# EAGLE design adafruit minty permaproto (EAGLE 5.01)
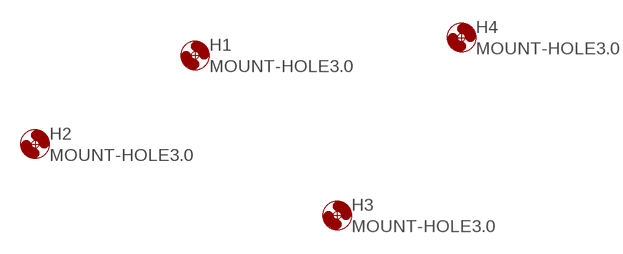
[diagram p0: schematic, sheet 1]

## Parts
H1  MOUNT-HOLE3.0  [3,0]
H2  MOUNT-HOLE3.0  [3,0]
H3  MOUNT-HOLE3.0  [3,0]
H4  MOUNT-HOLE3.0  [3,0]

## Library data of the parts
H1-H4 = holes:MOUNT-HOLE: MOUNTING HOLE with drill center marker

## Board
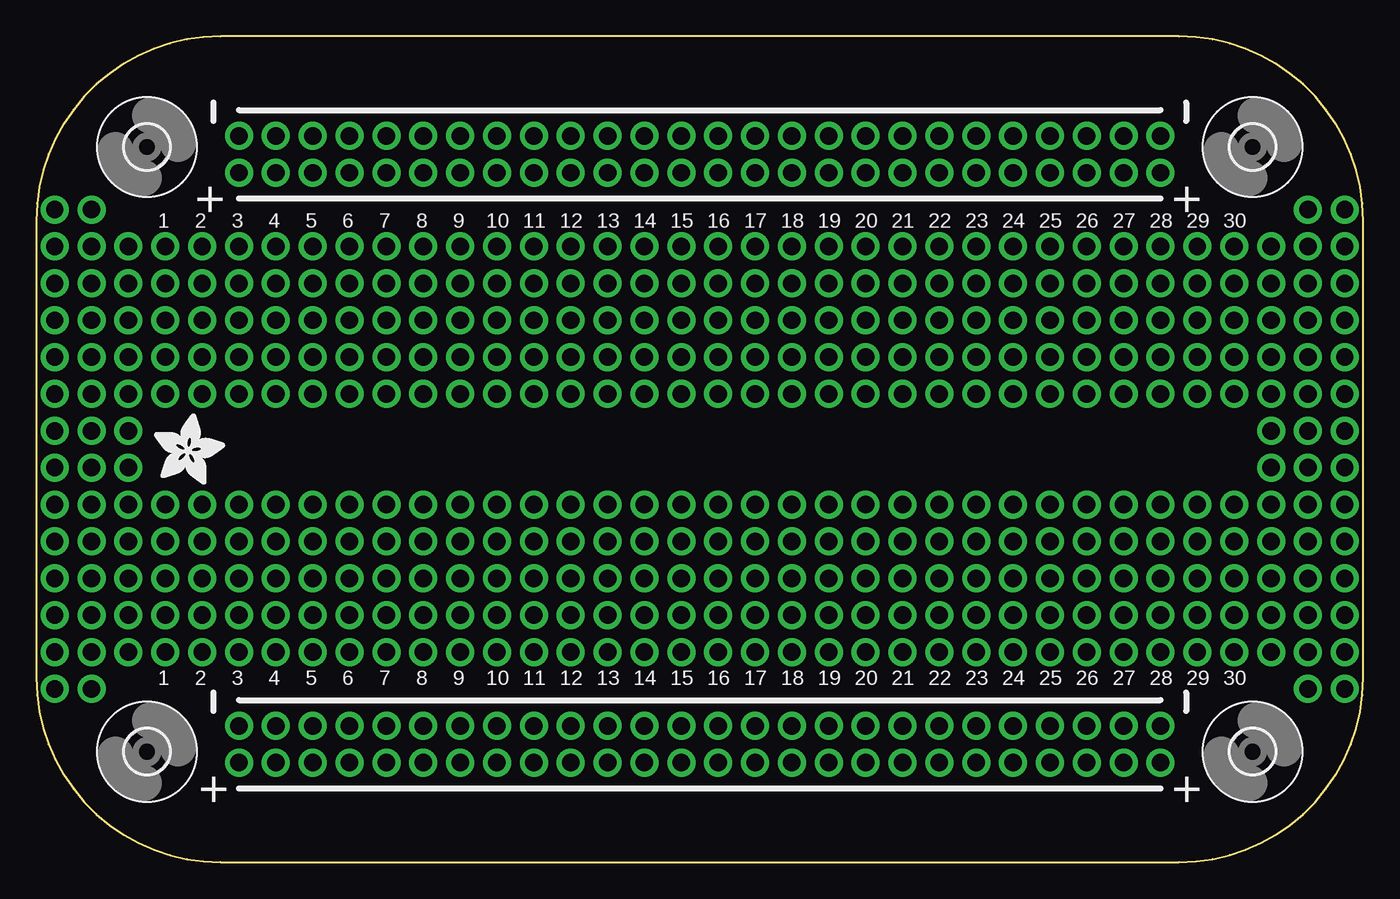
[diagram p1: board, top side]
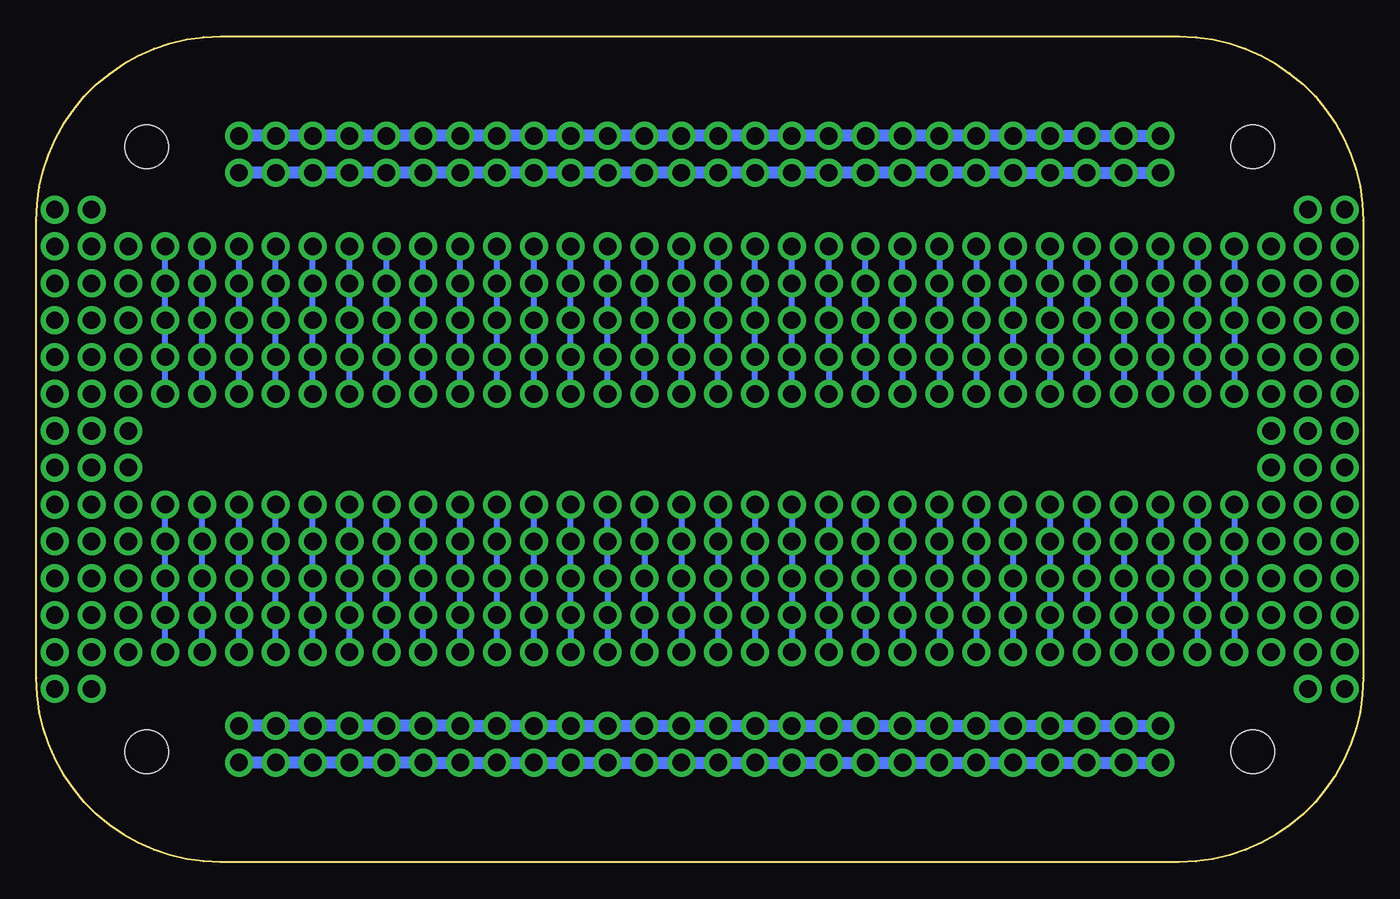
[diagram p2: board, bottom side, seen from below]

Size 91.44 x 56.9 mm. Coordinates in mm from the lower left corner, seen from the top.
Copper layers (1*16): Top 0.035mm / dielectric 1.5mm / Bottom 0.035mm
Design rules "default": minimum track width 10mil, minimum drill 24mil, track to track 8mil, track to pad 8mil, pad to pad 8mil, via to via 8mil, smd to smd 8mil, copper to edge 40mil, drill to drill 8mil, minimum pad ring 10mil, minimum via ring 8mil, stop-mask expansion 4mil, vias tented up to drill 0mil, thermal gap 10mil

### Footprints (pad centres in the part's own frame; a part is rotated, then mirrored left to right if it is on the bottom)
3,0 = hole 3: 0,0

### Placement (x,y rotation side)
H1  7.62,7.62 0 top
H2  83.82,7.62 0 top
H3  7.62,49.28 0 top
H4  83.82,49.28 0 top
U$2  [ALTOIDSTIN-DIM]  45.72,28.45 0 top
U$3  [ADAFRUIT_5MM]  8.13,26.04 0 top

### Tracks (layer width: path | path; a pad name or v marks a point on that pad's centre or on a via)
N$1  (via drill 1.2 pad 1.93)
  Bottom 0.406: v8.89,24.64 v8.89,22.1 v8.89,19.56 v8.89,17.02 v8.89,14.48
N$2  (via drill 1.2 pad 1.93)
  Bottom 0.406: v11.43,14.48 v11.43,17.02 v11.43,19.56 v11.43,22.1 v11.43,24.64
N$3  (via drill 1.2 pad 1.93)
  Bottom 0.406: v13.97,24.64 v13.97,22.1 v13.97,19.56 v13.97,17.02 v13.97,14.48
N$4  (via drill 1.2 pad 1.93)
  Bottom 0.406: v16.51,14.48 v16.51,17.02 v16.51,19.56 v16.51,22.1 v16.51,24.64
N$5  (via drill 1.2 pad 1.93)
  Bottom 0.406: v19.05,24.64 v19.05,22.1 v19.05,19.56 v19.05,17.02 v19.05,14.48
N$6  (via drill 1.2 pad 1.93)
  Bottom 0.406: v21.59,14.48 v21.59,17.02 v21.59,19.56 v21.59,22.1 v21.59,24.64
N$7  (via drill 1.2 pad 1.93)
  Bottom 0.406: v26.67,14.48 v26.67,17.02 v26.67,19.56 v26.67,22.1 v26.67,24.64
N$8  (via drill 1.2 pad 1.93)
  Bottom 0.406: v24.13,24.64 v24.13,22.1 v24.13,19.56 v24.13,17.02 v24.13,14.48
N$9  (via drill 1.2 pad 1.93)
  Bottom 0.406: v29.21,24.64 v29.21,22.1 v29.21,19.56 v29.21,17.02 v29.21,14.48
N$10  (via drill 1.2 pad 1.93)
  Bottom 0.406: v31.75,24.64 v31.75,22.1 v31.75,19.56 v31.75,17.02 v31.75,14.48
N$11  (via drill 1.2 pad 1.93)
  Bottom 0.406: v34.29,24.64 v34.29,22.1 v34.29,19.56 v34.29,17.02 v34.29,14.48
N$12  (via drill 1.2 pad 1.93)
  Bottom 0.406: v36.83,14.48 v36.83,17.02 v36.83,19.56 v36.83,22.1 v36.83,24.64
N$13  (via drill 1.2 pad 1.93)
  Bottom 0.406: v39.37,24.64 v39.37,22.1 v39.37,19.56 v39.37,17.02 v39.37,14.48
N$14  (via drill 1.2 pad 1.93)
  Bottom 0.406: v41.91,14.48 v41.91,17.02 v41.91,19.56 v41.91,22.1 v41.91,24.64
N$15  (via drill 1.2 pad 1.93)
  Bottom 0.406: v44.45,14.48 v44.45,17.02 v44.45,19.56 | v44.45,22.1 v44.45,19.56 | v44.45,24.64 v44.45,22.1 | v44.45,22.1 v44.45,19.56
N$16  (via drill 1.2 pad 1.93)
  Bottom 0.406: v46.99,24.64 v46.99,22.1 v46.99,19.56 v46.99,17.02 v46.99,14.48
N$17  (via drill 1.2 pad 1.93)
  Bottom 0.406: v52.07,24.64 v52.07,22.1 v52.07,19.56 v52.07,17.02 v52.07,14.48
N$18  (via drill 1.2 pad 1.93)
  Bottom 0.406: v49.53,14.48 v49.53,17.02 v49.53,19.56 v49.53,22.1 v49.53,24.64
N$19  (via drill 1.2 pad 1.93)
  Bottom 0.406: v54.61,24.64 v54.61,22.1 v54.61,19.56 v54.61,17.02 v54.61,14.48
N$20  (via drill 1.2 pad 1.93)
  Bottom 0.406: v57.15,14.48 v57.15,17.02 v57.15,19.56 v57.15,22.1 v57.15,24.64
N$21  (via drill 1.2 pad 1.93)
  Bottom 0.406: v62.23,14.48 v62.23,17.02 v62.23,19.56 v62.23,22.1 v62.23,24.64
N$22  (via drill 1.2 pad 1.93)
  Bottom 0.406: v59.69,24.64 v59.69,22.1 v59.69,19.56 v59.69,17.02 v59.69,14.48
N$23  (via drill 1.2 pad 1.93)
  Bottom 0.406: v64.77,24.64 v64.77,22.1 v64.77,19.56 v64.77,17.02 v64.77,14.48
N$24  (via drill 1.2 pad 1.93)
  Bottom 0.406: v67.31,14.48 v67.31,17.02 v67.31,19.56 v67.31,22.1 v67.31,24.64
N$25  (via drill 1.2 pad 1.93)
  Bottom 0.406: v69.85,24.64 v69.85,22.1 v69.85,19.56 v69.85,17.02 v69.85,14.48
N$26  (via drill 1.2 pad 1.93)
  Bottom 0.406: v72.39,14.48 v72.39,17.02 v72.39,19.56 v72.39,22.1 v72.39,24.64
N$27  (via drill 1.2 pad 1.93)
  Bottom 0.406: v77.47,24.64 v77.47,22.1 v77.47,19.56 v77.47,17.02 v77.47,14.48
N$28  (via drill 1.2 pad 1.93)
  Bottom 0.406: v74.93,14.48 v74.93,17.02 v74.93,19.56 v74.93,22.1 v74.93,24.64
N$29  (via drill 1.2 pad 1.93)
  Bottom 0.406: v80.01,24.64 v80.01,22.1 v80.01,19.56 v80.01,17.02 v80.01,14.48
N$30  (via drill 1.2 pad 1.93)
  Bottom 0.406: v82.55,14.48 v82.55,17.02 v82.55,19.56 v82.55,22.1 v82.55,24.64
N$31  (via drill 1.2 pad 1.93)
  Bottom 0.813: v13.97,9.4 v16.51,9.4 v19.05,9.4 v21.59,9.4 v24.13,9.4 v26.67,9.4 v29.21,9.4 v31.75,9.4 v34.29,9.4 v36.83,9.4 v39.37,9.4 v41.91,9.4 v44.45,9.4 v46.99,9.4 v49.53,9.4 v52.07,9.4 v54.61,9.4 | v74.93,9.4 v77.47,9.4 | v72.39,9.4 v74.93,9.4 | v72.39,9.4 v74.93,9.4 | v57.15,9.4 v54.61,9.4 | v57.15,9.4 v54.61,9.4 | v57.15,9.4 v59.69,9.4 v62.23,9.4 v64.77,9.4 v67.31,9.4 v69.85,9.4 v72.39,9.4
N$32  (via drill 1.2 pad 1.93)
  Bottom 0.813: v13.97,6.86 v16.51,6.86 v19.05,6.86 v21.59,6.86 v24.13,6.86 v26.67,6.86 v29.21,6.86 v31.75,6.86 v34.29,6.86 v36.83,6.86 v39.37,6.86 v41.91,6.86 v44.45,6.86 v46.99,6.86 v49.53,6.86 v52.07,6.86 v54.61,6.86 | v57.15,6.86 v54.61,6.86 | v57.15,6.86 v54.61,6.86 | v57.15,6.86 v59.69,6.86 v62.23,6.86 v64.77,6.86 v67.31,6.86 v69.85,6.86 v72.39,6.86 | v74.93,6.86 v77.47,6.86 | v72.39,6.86 v74.93,6.86 | v72.39,6.86 v74.93,6.86
N$33  (via drill 1.2 pad 1.93)
  Bottom 0.406: v82.55,32.26 v82.55,34.8 v82.55,37.34 v82.55,39.88 v82.55,42.42
N$34  (via drill 1.2 pad 1.93)
  Bottom 0.406: v80.01,42.42 v80.01,39.88 v80.01,37.34 v80.01,34.8 v80.01,32.26
N$35  (via drill 1.2 pad 1.93)
  Bottom 0.406: v77.47,32.26 v77.47,34.8 v77.47,37.34 v77.47,39.88 v77.47,42.42
N$36  (via drill 1.2 pad 1.93)
  Bottom 0.406: v74.93,42.42 v74.93,39.88 v74.93,37.34 v74.93,34.8 v74.93,32.26
N$37  (via drill 1.2 pad 1.93)
  Bottom 0.406: v72.39,32.26 v72.39,34.8 v72.39,37.34 v72.39,39.88 v72.39,42.42
N$38  (via drill 1.2 pad 1.93)
  Bottom 0.406: v69.85,42.42 v69.85,39.88 v69.85,37.34 v69.85,34.8 v69.85,32.26
N$39  (via drill 1.2 pad 1.93)
  Bottom 0.406: v64.77,42.42 v64.77,39.88 v64.77,37.34 v64.77,34.8 v64.77,32.26
N$40  (via drill 1.2 pad 1.93)
  Bottom 0.406: v67.31,32.26 v67.31,34.8 v67.31,37.34 v67.31,39.88 v67.31,42.42
N$41  (via drill 1.2 pad 1.93)
  Bottom 0.406: v62.23,32.26 v62.23,34.8 v62.23,37.34 v62.23,39.88 v62.23,42.42
N$42  (via drill 1.2 pad 1.93)
  Bottom 0.406: v59.69,32.26 v59.69,34.8 v59.69,37.34 v59.69,39.88 v59.69,42.42
N$43  (via drill 1.2 pad 1.93)
  Bottom 0.406: v57.15,32.26 v57.15,34.8 v57.15,37.34 v57.15,39.88 v57.15,42.42
N$44  (via drill 1.2 pad 1.93)
  Bottom 0.406: v54.61,42.42 v54.61,39.88 v54.61,37.34 v54.61,34.8 v54.61,32.26
N$45  (via drill 1.2 pad 1.93)
  Bottom 0.406: v52.07,32.26 v52.07,34.8 v52.07,37.34 v52.07,39.88 v52.07,42.42
N$46  (via drill 1.2 pad 1.93)
  Bottom 0.406: v49.53,42.42 v49.53,39.88 v49.53,37.34 v49.53,34.8 v49.53,32.26
N$47  (via drill 1.2 pad 1.93)
  Bottom 0.406: v46.99,42.42 v46.99,39.88 v46.99,37.34 | v46.99,34.8 v46.99,37.34 | v46.99,32.26 v46.99,34.8 | v46.99,34.8 v46.99,37.34
N$48  (via drill 1.2 pad 1.93)
  Bottom 0.406: v44.45,32.26 v44.45,34.8 v44.45,37.34 v44.45,39.88 v44.45,42.42
N$49  (via drill 1.2 pad 1.93)
  Bottom 0.406: v39.37,32.26 v39.37,34.8 v39.37,37.34 v39.37,39.88 v39.37,42.42
N$50  (via drill 1.2 pad 1.93)
  Bottom 0.406: v41.91,42.42 v41.91,39.88 v41.91,37.34 v41.91,34.8 v41.91,32.26
N$51  (via drill 1.2 pad 1.93)
  Bottom 0.406: v36.83,32.26 v36.83,34.8 v36.83,37.34 v36.83,39.88 v36.83,42.42
N$52  (via drill 1.2 pad 1.93)
  Bottom 0.406: v34.29,42.42 v34.29,39.88 v34.29,37.34 v34.29,34.8 v34.29,32.26
N$53  (via drill 1.2 pad 1.93)
  Bottom 0.406: v29.21,42.42 v29.21,39.88 v29.21,37.34 v29.21,34.8 v29.21,32.26
N$54  (via drill 1.2 pad 1.93)
  Bottom 0.406: v31.75,32.26 v31.75,34.8 v31.75,37.34 v31.75,39.88 v31.75,42.42
N$55  (via drill 1.2 pad 1.93)
  Bottom 0.406: v26.67,32.26 v26.67,34.8 v26.67,37.34 v26.67,39.88 v26.67,42.42
N$56  (via drill 1.2 pad 1.93)
  Bottom 0.406: v24.13,42.42 v24.13,39.88 v24.13,37.34 v24.13,34.8 v24.13,32.26
N$57  (via drill 1.2 pad 1.93)
  Bottom 0.406: v21.59,32.26 v21.59,34.8 v21.59,37.34 v21.59,39.88 v21.59,42.42
N$58  (via drill 1.2 pad 1.93)
  Bottom 0.406: v19.05,42.42 v19.05,39.88 v19.05,37.34 v19.05,34.8 v19.05,32.26
N$59  (via drill 1.2 pad 1.93)
  Bottom 0.406: v13.97,32.26 v13.97,34.8 v13.97,37.34 v13.97,39.88 v13.97,42.42
N$60  (via drill 1.2 pad 1.93)
  Bottom 0.406: v16.51,42.42 v16.51,39.88 v16.51,37.34 v16.51,34.8 v16.51,32.26
N$61  (via drill 1.2 pad 1.93)
  Bottom 0.406: v11.43,32.26 v11.43,34.8 v11.43,37.34 v11.43,39.88 v11.43,42.42
N$62  (via drill 1.2 pad 1.93)
  Bottom 0.406: v8.89,42.42 v8.89,39.88 v8.89,37.34 v8.89,34.8 v8.89,32.26
N$63  (via drill 1.2 pad 1.93)
  Bottom 0.813: v77.47,47.5 v74.93,47.5 v72.39,47.5 v69.85,47.5 v67.31,47.5 v64.77,47.5 v62.23,47.5 v59.69,47.5 v57.15,47.5 v54.61,47.5 v52.07,47.5 v49.53,47.5 v46.99,47.5 v44.45,47.5 v41.91,47.5 v39.37,47.5 v36.83,47.5 | v16.51,47.5 v13.97,47.5 | v19.05,47.5 v16.51,47.5 | v19.05,47.5 v16.51,47.5 | v34.29,47.5 v36.83,47.5 | v34.29,47.5 v36.83,47.5 | v34.29,47.5 v31.75,47.5 v29.21,47.5 v26.67,47.5 v24.13,47.5 v21.59,47.5 v19.05,47.5
N$64  (via drill 1.2 pad 1.93)
  Bottom 0.813: v77.47,50.04 v74.93,50.04 v72.39,50.04 v69.85,50.04 v67.31,50.04 v64.77,50.04 v62.23,50.04 v59.69,50.04 v57.15,50.04 v54.61,50.04 v52.07,50.04 v49.53,50.04 v46.99,50.04 v44.45,50.04 v41.91,50.04 v39.37,50.04 v36.83,50.04 | v34.29,50.04 v36.83,50.04 | v34.29,50.04 v36.83,50.04 | v34.29,50.04 v31.75,50.04 v29.21,50.04 v26.67,50.04 v24.13,50.04 v21.59,50.04 v19.05,50.04 | v16.51,50.04 v13.97,50.04 | v19.05,50.04 v16.51,50.04 | v19.05,50.04 v16.51,50.04
N$65  (via drill 1.2 pad 1.93)
  other vias: 6.35,42.42
N$66  (via drill 1.2 pad 1.93)
  other vias: 6.35,39.88
N$67  (via drill 1.2 pad 1.93)
  other vias: 6.35,37.34
N$68  (via drill 1.2 pad 1.93)
  other vias: 6.35,34.8
N$69  (via drill 1.2 pad 1.93)
  other vias: 6.35,32.26
N$70  (via drill 1.2 pad 1.93)
  other vias: 3.81,32.26
N$71  (via drill 1.2 pad 1.93)
  other vias: 3.81,34.8
N$72  (via drill 1.2 pad 1.93)
  other vias: 3.81,37.34
N$73  (via drill 1.2 pad 1.93)
  other vias: 3.81,39.88
N$74  (via drill 1.2 pad 1.93)
  other vias: 3.81,42.42
N$75  (via drill 1.2 pad 1.93)
  other vias: 3.81,44.96
N$76  (via drill 1.2 pad 1.93)
  other vias: 1.27,44.96
N$77  (via drill 1.2 pad 1.93)
  other vias: 1.27,42.42
N$78  (via drill 1.2 pad 1.93)
  other vias: 1.27,39.88
N$79  (via drill 1.2 pad 1.93)
  other vias: 1.27,37.34
N$80  (via drill 1.2 pad 1.93)
  other vias: 1.27,34.8
N$81  (via drill 1.2 pad 1.93)
  other vias: 1.27,32.26
N$82  (via drill 1.2 pad 1.93)
  other vias: 1.27,29.72
N$83  (via drill 1.2 pad 1.93)
  other vias: 3.81,29.72
N$84  (via drill 1.2 pad 1.93)
  other vias: 3.81,27.18
N$85  (via drill 1.2 pad 1.93)
  other vias: 1.27,27.18
N$86  (via drill 1.2 pad 1.93)
  other vias: 1.27,22.1
N$87  (via drill 1.2 pad 1.93)
  other vias: 3.81,24.64
N$88  (via drill 1.2 pad 1.93)
  other vias: 3.81,22.1
N$89  (via drill 1.2 pad 1.93)
  other vias: 1.27,24.64
N$90  (via drill 1.2 pad 1.93)
  other vias: 6.35,29.72
N$91  (via drill 1.2 pad 1.93)
  other vias: 6.35,27.18
N$92  (via drill 1.2 pad 1.93)
  other vias: 6.35,24.64
N$93  (via drill 1.2 pad 1.93)
  other vias: 6.35,22.1
N$94  (via drill 1.2 pad 1.93)
  other vias: 6.35,19.56
N$95  (via drill 1.2 pad 1.93)
  other vias: 6.35,17.02
N$96  (via drill 1.2 pad 1.93)
  other vias: 6.35,14.48
N$97  (via drill 1.2 pad 1.93)
  other vias: 3.81,14.48
N$98  (via drill 1.2 pad 1.93)
  other vias: 3.81,17.02
N$99  (via drill 1.2 pad 1.93)
  other vias: 3.81,19.56
N$100  (via drill 1.2 pad 1.93)
  other vias: 1.27,19.56
N$101  (via drill 1.2 pad 1.93)
  other vias: 1.27,17.02
N$102  (via drill 1.2 pad 1.93)
  other vias: 1.27,14.48
N$103  (via drill 1.2 pad 1.93)
  other vias: 3.81,11.94
N$104  (via drill 1.2 pad 1.93)
  other vias: 1.27,11.94
N$105  (via drill 1.2 pad 1.93)
  other vias: 85.09,42.42
N$106  (via drill 1.2 pad 1.93)
  other vias: 85.09,39.88
N$107  (via drill 1.2 pad 1.93)
  other vias: 85.09,37.34
N$108  (via drill 1.2 pad 1.93)
  other vias: 85.09,34.8
N$109  (via drill 1.2 pad 1.93)
  other vias: 85.09,32.26
N$110  (via drill 1.2 pad 1.93)
  other vias: 85.09,27.18
N$111  (via drill 1.2 pad 1.93)
  other vias: 85.09,22.1
N$112  (via drill 1.2 pad 1.93)
  other vias: 85.09,19.56
N$113  (via drill 1.2 pad 1.93)
  other vias: 85.09,17.02
N$114  (via drill 1.2 pad 1.93)
  other vias: 85.09,14.48
N$115  (via drill 1.2 pad 1.93)
  other vias: 87.63,11.94
N$116  (via drill 1.2 pad 1.93)
  other vias: 87.63,14.48
N$117  (via drill 1.2 pad 1.93)
  other vias: 87.63,17.02
N$118  (via drill 1.2 pad 1.93)
  other vias: 90.17,19.56
N$119  (via drill 1.2 pad 1.93)
  other vias: 87.63,19.56
N$120  (via drill 1.2 pad 1.93)
  other vias: 87.63,22.1
N$121  (via drill 1.2 pad 1.93)
  other vias: 90.17,22.1
N$122  (via drill 1.2 pad 1.93)
  other vias: 90.17,27.18
N$123  (via drill 1.2 pad 1.93)
  other vias: 87.63,24.64
N$124  (via drill 1.2 pad 1.93)
  other vias: 85.09,29.72
N$125  (via drill 1.2 pad 1.93)
  other vias: 85.09,24.64
N$126  (via drill 1.2 pad 1.93)
  other vias: 87.63,27.18
N$127  (via drill 1.2 pad 1.93)
  other vias: 90.17,24.64
N$128  (via drill 1.2 pad 1.93)
  other vias: 90.17,29.72
N$129  (via drill 1.2 pad 1.93)
  other vias: 87.63,29.72
N$130  (via drill 1.2 pad 1.93)
  other vias: 87.63,32.26
N$131  (via drill 1.2 pad 1.93)
  other vias: 90.17,32.26
N$132  (via drill 1.2 pad 1.93)
  other vias: 90.17,34.8
N$133  (via drill 1.2 pad 1.93)
  other vias: 87.63,34.8
N$134  (via drill 1.2 pad 1.93)
  other vias: 87.63,37.34
N$135  (via drill 1.2 pad 1.93)
  other vias: 90.17,37.34
N$136  (via drill 1.2 pad 1.93)
  other vias: 90.17,39.88
N$137  (via drill 1.2 pad 1.93)
  other vias: 87.63,39.88
N$138  (via drill 1.2 pad 1.93)
  other vias: 87.63,42.42
N$139  (via drill 1.2 pad 1.93)
  other vias: 90.17,42.42
N$140  (via drill 1.2 pad 1.93)
  other vias: 90.17,44.96
N$141  (via drill 1.2 pad 1.93)
  other vias: 87.63,44.96
N$142  (via drill 1.2 pad 1.93)
  other vias: 90.17,17.02
N$143  (via drill 1.2 pad 1.93)
  other vias: 90.17,14.48
N$144  (via drill 1.2 pad 1.93)
  other vias: 90.17,11.94

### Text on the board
tPlace: 1 | 2 | 3 | 4 | 5 | 6 | 7 | 8 | 9 | 10 | 11 | 12 | 13 | 14 | 15 | 16 | 17 | 18 | 19 | 20 | 21 | 22 | 23 | 24 | 25 | 26 | 27 | 28 | 29 | 30 | 1 | 2 | 3 | 4 | 5 | 6 | 7 | 8 | 9 | 10 | 11 | 12 | 13 | 14 | 15 | 16 | 17 | 18 | 19 | 20 | 21 | 22 | 23 | 24 | 25 | 26 | 27 | 28 | 29 | 30
tDocu: Adafruit Mint Tin-Sized PermaProto Breadboard
tPlaceRed: + | + | + | +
